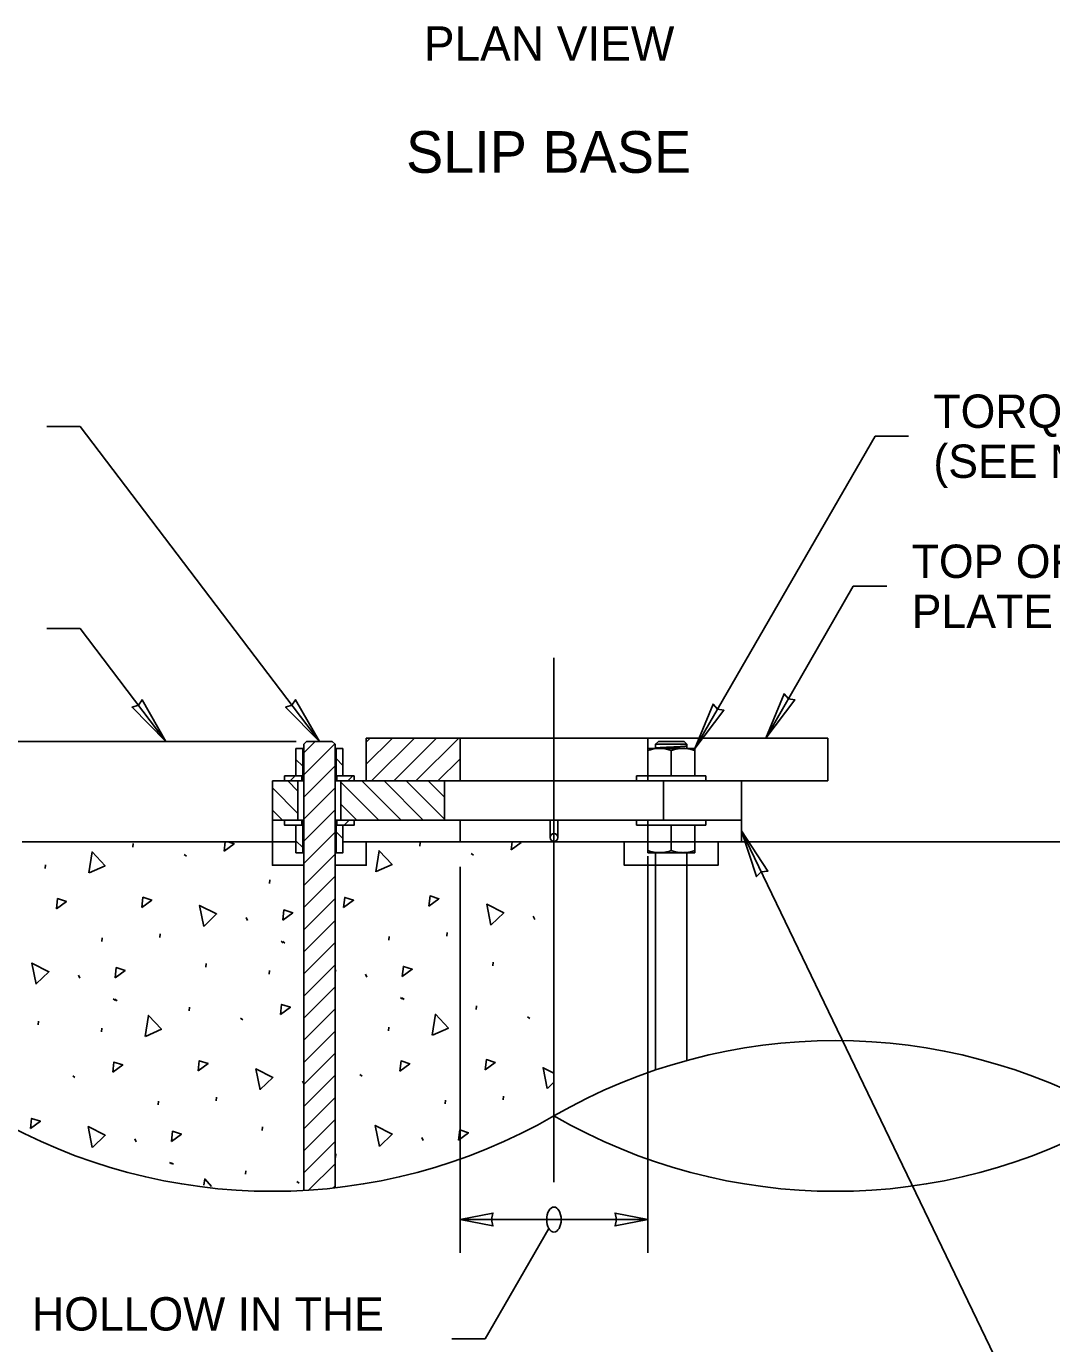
# Model space of a CAD drawing. Extents: x 99862 to 104211, y 98939 to 102076.
# Drawn here: x 100841 to 101332, y 100339 to 100970 of the extents above; entities that cross this region are included whole.
import ezdxf

# ---------------------------------------------------------------- set-up
doc = ezdxf.new("R2010")
doc.units = 0
for name, color, linetype in [('Level 1', 7, 'Continuous'), ('Level 12', 7, 'Continuous'), ('Level 13', 7, 'Continuous'), ('Level 15', 7, 'Continuous'), ('Level 20', 7, 'Continuous'), ('Level 3', 7, 'Continuous'), ('Level 4', 7, 'Continuous'), ('Level 62', 7, 'Continuous'), ('Level 8', 7, 'Continuous'), ('Level 9', 7, 'Continuous')]:
    doc.layers.add(name, color=color, linetype=linetype)

msp = doc.modelspace()

# ---------------------------------------------------------------- linework, layer by layer
at = {"layer": 'Level 1'}
for centre, start, end in [((101228.69, 100213.97), 60, 120), ((100958.69, 100681.63), 240, 300), ((101228.69, 100681.63), 240, 300)]:
    msp.add_arc(centre, 270, start, end, dxfattribs=at)
at = {"layer": 'Level 12'}
for p, q in [((100958.69, 100579.31), (100958.69, 100589.72)), ((101091.82, 100581.35), (101091.82, 100589.72)), ((101095.57, 100581.35), (101095.57, 100589.72)), ((101138.69, 100579.31), (101138.69, 100589.72)), ((101183.69, 100579.31), (101183.69, 100589.72))]:
    msp.add_line(p, q, dxfattribs=at)
for points in [[(100969.94, 100587.22), (100964.52, 100587.22), (100964.52, 100589.72), (100963.51, 100589.72), (100958.69, 100589.72), (100958.69, 100579.31), (100958.69, 100579.31), (100958.69, 100568.06), (100973.69, 100568.06), (100973.69, 100571.45), (100973.69, 100574.09), (100973.22, 100574.09), (100969.94, 100574.09), (100969.94, 100579.8), (100969.94, 100587.22)], [(100992.99, 100587.22), (100992.44, 100587.22), (100992.44, 100580.88), (100992.44, 100574.09), (100989.16, 100574.09), (100988.69, 100574.09), (100988.69, 100571.66), (100988.69, 100569.16), (100988.69, 100568.06), (101003.69, 100568.06), (101003.69, 100579.31), (101048.69, 100579.31), (101048.69, 100589.72), (101041.19, 100589.72), (101030.96, 100589.72), (101020.35, 100589.72), (101009.74, 100589.72), (100999.14, 100589.72), (100997.86, 100589.72), (100997.86, 100587.22), (100992.99, 100587.22)], [(101172.44, 100579.31), (101183.69, 100579.31), (101183.69, 100589.72), (101138.69, 100589.72), (101093.69, 100589.72), (101093.69, 100579.31), (101127.44, 100579.31), (101172.44, 100579.31)], [(101161.46, 100579.31), (101138.69, 100579.31), (101138.41, 100579.31), (101127.44, 100579.31), (101127.44, 100568.06), (101172.44, 100568.06), (101172.44, 100579.31), (101161.46, 100579.31)]]:
    msp.add_lwpolyline(points, dxfattribs=at)
msp.add_circle((101093.69, 100581.35), 1.88, dxfattribs=at)
at = {"layer": 'Level 13'}
for p, q in [((100891.68, 100576.69), (100891.83, 100578.43)), ((101029.37, 100577.26), (101029.52, 100579)), ((100916.37, 100573.17), (100917.39, 100572.39)), ((101054.06, 100573.74), (101055.08, 100572.97)), ((100849.71, 100566.55), (100849.86, 100568.3)), ((100957.23, 100559.25), (100957.38, 100560.99)), ((100946.06, 100542.98), (100946.75, 100541.53)), ((101083.76, 100543.56), (101084.44, 100542.11)), ((100876.79, 100531.55), (100876.94, 100533.29)), ((100904.69, 100533.45), (100904.84, 100535.2)), ((101014.48, 100532.13), (101014.63, 100533.87)), ((101042.38, 100534.03), (101042.53, 100535.77)), ((100962.78, 100531.67), (100963.8, 100530.89)), ((100963.58, 100531.52), (100964.6, 100530.74)), ((100926.68, 100519.24), (100926.83, 100520.98)), ((101064.37, 100519.81), (101064.52, 100521.56)), ((100865.62, 100515.29), (100866.31, 100513.83)), ((100957.16, 100515.81), (100957.31, 100517.55)), ((101003.32, 100515.86), (101004, 100514.41)), ((100882.34, 100503.97), (100883.36, 100503.19)), ((100883.14, 100503.82), (100884.16, 100503.04)), ((101020.03, 100504.55), (101021.05, 100503.77)), ((101020.84, 100504.4), (101021.85, 100503.62)), ((100918.69, 100498.24), (100918.84, 100499.99)), ((101056.38, 100498.82), (101056.53, 100500.56)), ((101081.07, 100495.3), (101082.09, 100494.52)), ((100846.24, 100491.54), (100846.39, 100493.28)), ((100876.72, 100488.11), (100876.87, 100489.85)), ((100943.38, 100494.72), (100944.4, 100493.95)), ((101014.41, 100488.69), (101014.56, 100490.43)), ((100862.94, 100467.03), (100863.96, 100466.25)), ((100973.07, 100464.54), (100973.69, 100463.24)), ((101000.63, 100467.6), (101001.65, 100466.83)), ((101069.39, 100455.59), (101069.54, 100457.33)), ((100903.8, 100453.11), (100903.95, 100454.85)), ((100931.7, 100455.01), (100931.85, 100456.75)), ((101041.49, 100453.68), (101041.64, 100455.43)), ((100953.69, 100440.79), (100953.84, 100442.54)), ((100892.63, 100436.84), (100893.32, 100435.39)), ((101030.33, 100437.42), (101031.01, 100435.97)), ((100909.35, 100425.53), (100910.37, 100424.75)), ((100988.95, 100427.89), (100989.1, 100429.63)), ((100910.15, 100425.38), (100911.17, 100424.6)), ((100945.7, 100419.8), (100945.85, 100421.54)), ((100970.39, 100416.28), (100971.41, 100415.5))]:
    msp.add_line(p, q, dxfattribs=at)
for points in [[(100935.51, 100574.87), (100936.02, 100579.31)], [(100937.48, 100579.31), (100940.3, 100578.4), (100935.51, 100574.87)], [(101073.2, 100575.45), (101073.65, 100579.31)], [(101076.96, 100579.31), (101077.99, 100578.98), (101073.2, 100575.45)], [(100870.57, 100564.35), (100872.16, 100574.47), (100878.4, 100567.79), (100870.74, 100564.4)], [(101008.26, 100564.92), (101009.85, 100575.05), (101016.09, 100568.37), (101008.43, 100564.98)], [(100855.07, 100547.17), (100855.64, 100552.07), (100859.86, 100550.7), (100855.07, 100547.17)], [(100896.01, 100547.85), (100896.58, 100552.74), (100900.81, 100551.37), (100896.01, 100547.85)], [(100992.76, 100547.75), (100993.33, 100552.64), (100997.55, 100551.28), (100992.76, 100547.75)], [(101033.7, 100548.42), (101034.27, 100553.31), (101038.5, 100551.95), (101033.7, 100548.42)], [(100925.71, 100538.75), (100923.74, 100548.81), (100931.89, 100544.67), (100925.85, 100538.86)], [(100963.64, 100541.73), (100964.21, 100546.62), (100968.43, 100545.26), (100963.64, 100541.73)], [(101063.41, 100539.33), (101061.43, 100549.38), (101069.58, 100545.24), (101063.54, 100539.44)], [(100845.27, 100511.05), (100843.3, 100521.11), (100851.45, 100516.97), (100845.41, 100511.17)], [(100883.2, 100514.03), (100883.77, 100518.93), (100887.99, 100517.56), (100883.2, 100514.03)], [(100988.69, 100517.78), (100989.14, 100517.55), (100988.69, 100517.11)], [(101020.89, 100514.61), (101021.46, 100519.5), (101025.69, 100518.14), (101020.89, 100514.61)], [(100962.52, 100496.43), (100963.09, 100501.32), (100967.31, 100499.96), (100962.52, 100496.43)], [(100897.58, 100485.9), (100899.17, 100496.03), (100905.41, 100489.35), (100897.75, 100485.96)], [(101035.27, 100486.48), (101036.86, 100496.6), (101043.1, 100489.93), (101035.44, 100486.54)], [(100882.08, 100468.73), (100882.65, 100473.62), (100886.87, 100472.26), (100882.08, 100468.73)], [(100923.02, 100469.4), (100923.59, 100474.29), (100927.82, 100472.93), (100923.02, 100469.4)], [(100952.72, 100460.31), (100950.75, 100470.36), (100958.9, 100466.23), (100952.86, 100460.42)], [(101019.77, 100469.31), (101020.34, 100474.2), (101024.56, 100472.84), (101019.77, 100469.31)], [(101060.71, 100469.98), (101061.28, 100474.87), (101065.51, 100473.51), (101060.71, 100469.98)], [(101090.42, 100460.88), (101088.44, 100470.94), (101093.69, 100468.28)], [(101093.69, 100464.01), (101090.55, 100461)], [(100842.58, 100441.7), (100843.15, 100446.6), (100847.38, 100445.23), (100842.58, 100441.7)], [(100872.28, 100432.61), (100870.31, 100442.67), (100878.46, 100438.53), (100872.42, 100432.72)], [(100910.21, 100435.59), (100910.78, 100440.48), (100915, 100439.12), (100910.21, 100435.59)], [(101009.98, 100433.19), (101008, 100443.24), (101016.15, 100439.1), (101010.11, 100433.3)], [(101047.9, 100436.17), (101048.47, 100441.06), (101052.7, 100439.7), (101047.9, 100436.17)], [(100925.69, 100414.51), (100926.18, 100417.59), (100929.51, 100414.02)]]:
    msp.add_lwpolyline(points, dxfattribs=at)
at = {"layer": 'Level 15'}
for p, q in [((100850.4, 100778.53), (100866.4, 100778.53)), ((100981.19, 100627.44), (100866.4, 100778.53)), ((101161.19, 100624.09), (101247.67, 100773.87)), ((101247.67, 100773.87), (101263.67, 100773.87)), ((101195.25, 100629.09), (101237.27, 100701.87)), ((101237.27, 100701.87), (101253.27, 100701.87)), ((100850.4, 100681.6), (100866.4, 100681.6)), ((100907.55, 100627.44), (100866.4, 100681.6)), ((100970.05, 100627.44), (100775.27, 100627.44)), ((101183.69, 100584.51), (101310.37, 100321.47)), ((101138.69, 100572.34), (101138.69, 100382.09)), ((101048.69, 100567.31), (101048.69, 100382.09)), ((101091.24, 100393.85), (101060.64, 100340.85)), ((101044.64, 100340.85), (101060.64, 100340.85))]:
    msp.add_line(p, q, dxfattribs=at)
for points in [[(100907.55, 100627.44), (100891.37, 100643.81), (100894.38, 100644.78), (100896.12, 100647.42)], [(100981.19, 100627.44), (100965, 100643.81), (100968.02, 100644.78), (100969.76, 100647.42)], [(101195.25, 100629.09), (101204.08, 100650.35), (101206.14, 100647.95), (101209.25, 100647.37)], [(101161.19, 100624.09), (101170.02, 100645.35), (101172.07, 100642.95), (101175.19, 100642.37)], [(101183.69, 100584.51), (101196.29, 100565.24), (101193.14, 100564.9), (101190.91, 100562.65)]]:
    msp.add_lwpolyline(points, close=True, dxfattribs=at)
msp.add_ellipse((101093.69, 100398.09), major_axis=(0, -6), ratio=0.57735, dxfattribs=at)
at = {"layer": 'Level 3'}
for p, q in [((100958.69, 100608.47), (100958.69, 100589.72)), ((100970.88, 100608.47), (100958.69, 100608.47)), ((100958.69, 100605.14), (100970.88, 100592.95)), ((100965.97, 100608.47), (100970.88, 100603.55)), ((100970.88, 100608.47), (100970.88, 100589.72)), ((100970.88, 100608.47), (100973.69, 100608.47)), ((100988.69, 100608.47), (100991.5, 100608.47)), ((101003.69, 100608.47), (100991.5, 100608.47)), ((100991.5, 100608.47), (100991.5, 100589.72)), ((100991.5, 100607.95), (101009.74, 100589.72)), ((101001.6, 100608.47), (101020.35, 100589.72)), ((101012.21, 100608.47), (101030.96, 100589.72)), ((101022.81, 100608.47), (101041.19, 100590.09)), ((101033.42, 100608.47), (101041.19, 100600.69)), ((101041.19, 100589.72), (101041.19, 100608.47)), ((101183.69, 100608.47), (101048.69, 100608.47)), ((101146.19, 100589.72), (101146.19, 100608.47)), ((101183.41, 100608.47), (101183.69, 100608.19)), ((101183.69, 100589.72), (101183.69, 100608.47)), ((100991.5, 100597.35), (100999.14, 100589.72)), ((100958.69, 100594.53), (100963.51, 100589.72)), ((100958.69, 100589.72), (100970.88, 100589.72)), ((100970.88, 100589.72), (100973.69, 100589.72)), ((100988.69, 100589.72), (100991.5, 100589.72)), ((100991.5, 100589.72), (101041.19, 100589.72)), ((101183.69, 100589.72), (101041.19, 100589.72))]:
    msp.add_line(p, q, dxfattribs=at)
at = {"layer": 'Level 4'}
for p, q in [((101048.69, 100629.09), (101003.69, 100629.09)), ((101003.69, 100608.47), (101003.69, 100629.09)), ((101003.69, 100627.17), (101005.61, 100629.09)), ((101003.69, 100616.56), (101016.22, 100629.09)), ((101006.2, 100608.47), (101026.83, 100629.09)), ((101016.81, 100608.47), (101037.43, 100629.09)), ((101027.41, 100608.47), (101048.04, 100629.09)), ((101048.69, 100608.47), (101048.69, 100629.09)), ((101093.69, 100629.09), (101048.69, 100629.09)), ((101224.98, 100629.09), (101093.69, 100629.09)), ((101138.69, 100608.47), (101138.69, 100629.09)), ((101224.98, 100608.47), (101224.98, 100629.09)), ((101038.02, 100608.47), (101048.69, 100619.14)), ((101048.69, 100608.47), (101003.69, 100608.47)), ((101048.63, 100608.47), (101048.69, 100608.53)), ((101224.98, 100608.47), (101183.69, 100608.47)), ((101138.69, 100398.09), (101048.69, 100398.09))]:
    msp.add_line(p, q, dxfattribs=at)
for points in [[(101048.69, 100398.09), (101064.42, 100395.01), (101063.69, 100398.09), (101064.42, 100401.18)], [(101138.69, 100398.09), (101122.97, 100395.01), (101123.69, 100398.09), (101122.97, 100401.18)]]:
    msp.add_lwpolyline(points, close=True, dxfattribs=at)
at = {"layer": 'Level 62'}
for points, degree in [([(100988.69, 100624.18), (100988.74, 100624.15), (100988.73, 100624.12), (100988.66, 100624.09)], 3), ([(101142.44, 100624.09), (101142.17, 100624.3), (101144.21, 100624.47), (101147.28, 100624.61), (101153.2, 100624.88), (101158.21, 100625.15), (101157.44, 100625.43)], 4), ([(101157.44, 100624.18), (101157.49, 100624.15), (101157.48, 100624.12), (101157.41, 100624.09)], 3), ([(100988.69, 100571.66), (100988.71, 100571.65), (100988.72, 100571.64), (100988.72, 100571.62)], 3), ([(101157.44, 100574), (101157.49, 100574.03), (101157.48, 100574.06), (101157.41, 100574.09)], 3), ([(101157.44, 100574), (101157.49, 100574.03), (101157.48, 100574.06), (101157.41, 100574.09)], 3), ([(100988.69, 100569.16), (100988.71, 100569.14), (100988.71, 100569.13), (100988.71, 100569.12)], 3)]:
    msp.add_open_spline(points, degree=degree, dxfattribs=at)
at = {"layer": 'Level 8'}
for p, q in [((101048.69, 100579.31), (101048.69, 100589.72)), ((100958.69, 100579.31), (100838.69, 100579.31)), ((100958.69, 100579.31), (100958.69, 100568.06)), ((100958.69, 100579.31), (100969.66, 100579.31)), ((101003.69, 100579.31), (100992.71, 100579.31)), ((101093.69, 100579.31), (101003.69, 100579.31)), ((101003.69, 100579.31), (101003.69, 100568.06)), ((101093.69, 100579.31), (101127.44, 100579.31)), ((101127.44, 100579.31), (101127.44, 100568.06)), ((101127.44, 100579.31), (101127.44, 100568.06)), ((101127.44, 100579.31), (101138.41, 100579.31)), ((101172.44, 100579.31), (101161.46, 100579.31)), ((101172.44, 100579.31), (101348.69, 100579.31)), ((101172.44, 100579.31), (101172.44, 100568.06)), ((101172.44, 100579.31), (101172.44, 100568.06)), ((100973.69, 100568.06), (100958.69, 100568.06)), ((101003.69, 100568.06), (100988.69, 100568.06)), ((101172.44, 100568.06), (101127.44, 100568.06)), ((101172.44, 100568.06), (101127.44, 100568.06))]:
    msp.add_line(p, q, dxfattribs=at)
at = {"layer": 'Level 9'}
for p, q in [((101093.69, 100667.59), (101093.69, 100416.08)), ((100969.94, 100624.09), (100973.22, 100624.09)), ((100969.94, 100624.09), (100969.94, 100610.97)), ((100973.22, 100624.09), (100973.22, 100608.47)), ((100975.02, 100627.44), (100973.69, 100626.11)), ((100973.69, 100621.99), (100979.14, 100627.44)), ((100973.69, 100611.38), (100988.56, 100626.25)), ((100973.69, 100626.11), (100973.69, 100412.04)), ((100975.02, 100627.44), (100987.37, 100627.44)), ((100988.69, 100626.11), (100987.37, 100627.44)), ((100988.69, 100413.3), (100988.69, 100626.11)), ((100989.16, 100624.09), (100992.44, 100624.09)), ((100989.16, 100608.47), (100989.16, 100624.09)), ((100992.44, 100624.09), (100992.44, 100610.97)), ((101138.69, 100624.09), (101155.44, 100624.09)), ((101138.69, 100623.08), (101138.69, 100610.97)), ((101143.77, 100627.44), (101142.44, 100626.11)), ((101142.44, 100626.11), (101157.44, 100626.11)), ((101142.44, 100626.11), (101142.44, 100624.09)), ((101143.77, 100627.44), (101156.12, 100627.44)), ((101149.94, 100623.09), (101149.94, 100610.97)), ((101155.69, 100624.09), (101155.44, 100624.09)), ((101155.69, 100624.09), (101161.19, 100624.09)), ((101157.44, 100626.11), (101156.12, 100627.44)), ((101157.44, 100624.09), (101157.44, 100626.11)), ((101161.19, 100623.09), (101161.19, 100610.97)), ((100969.94, 100618.81), (100973.22, 100615.53)), ((100973.69, 100600.77), (100988.69, 100615.77)), ((100989.16, 100619.26), (100992.44, 100615.98)), ((100964.52, 100610.97), (100964.52, 100608.47)), ((100972.75, 100610.97), (100964.52, 100610.97)), ((100967.1, 100608.47), (100969.6, 100610.97)), ((100972.75, 100610.97), (100972.75, 100608.47)), ((100973.22, 100610.97), (100972.75, 100610.97)), ((100989.63, 100610.97), (100989.16, 100610.97)), ((100989.63, 100608.47), (100989.63, 100610.97)), ((100997.86, 100610.97), (100989.63, 100610.97)), ((100994.8, 100608.47), (100997.3, 100610.97)), ((100997.86, 100610.97), (100997.86, 100608.47)), ((101166.61, 100610.97), (101133.27, 100610.97)), ((101133.27, 100610.97), (101133.27, 100608.47)), ((101149.94, 100610.97), (101138.69, 100610.97)), ((101161.19, 100610.97), (101149.94, 100610.97)), ((101166.61, 100610.97), (101166.61, 100608.47)), ((100973.69, 100590.17), (100988.69, 100605.17)), ((100973.69, 100579.56), (100988.69, 100594.56)), ((100964.52, 100587.22), (100964.52, 100589.72)), ((100972.75, 100587.22), (100964.52, 100587.22)), ((100969.94, 100574.09), (100969.94, 100587.22)), ((100972.23, 100587.22), (100972.75, 100587.74)), ((100972.75, 100587.22), (100972.75, 100589.72)), ((100973.22, 100587.22), (100972.75, 100587.22)), ((100973.22, 100587.22), (100973.22, 100589.72)), ((100973.22, 100574.09), (100973.22, 100587.22)), ((100973.69, 100568.95), (100988.69, 100583.95)), ((100989.16, 100589.72), (100989.16, 100587.22)), ((100992.44, 100587.22), (100989.16, 100587.22)), ((100989.16, 100587.22), (100989.16, 100574.09)), ((100989.16, 100584.15), (100992.44, 100580.88)), ((100989.63, 100589.72), (100989.63, 100587.22)), ((100992.44, 100574.09), (100992.44, 100587.22)), ((100997.86, 100587.22), (100992.44, 100587.22)), ((100992.99, 100587.22), (100995.49, 100589.72)), ((100997.86, 100587.22), (100997.86, 100589.72)), ((101133.27, 100587.22), (101133.27, 100589.72)), ((101133.27, 100587.22), (101133.27, 100589.72)), ((101166.61, 100587.22), (101133.27, 100587.22)), ((101166.61, 100587.22), (101133.27, 100587.22)), ((101138.69, 100575.1), (101138.69, 100587.22)), ((101138.69, 100575.1), (101138.69, 100587.22)), ((101149.94, 100575.09), (101149.94, 100587.22)), ((101149.94, 100575.09), (101149.94, 100587.22)), ((101161.19, 100575.09), (101161.19, 100587.22)), ((101161.19, 100575.09), (101161.19, 100587.22)), ((101166.61, 100587.22), (101166.61, 100589.72)), ((101166.61, 100587.22), (101166.61, 100589.72)), ((100969.94, 100579.8), (100973.22, 100576.52)), ((100969.94, 100574.09), (100973.22, 100574.09)), ((100973.22, 100574.09), (100973.69, 100574.09)), ((100973.69, 100558.35), (100988.69, 100573.35)), ((100988.69, 100574.09), (100989.16, 100574.09)), ((100989.16, 100574.09), (100992.44, 100574.09)), ((101138.69, 100574.09), (101155.44, 100574.09)), ((101138.69, 100574.09), (101155.44, 100574.09)), ((101142.44, 100469.82), (101142.44, 100574.09)), ((101155.69, 100574.09), (101155.44, 100574.09)), ((101155.69, 100574.09), (101155.44, 100574.09)), ((101155.69, 100574.09), (101161.19, 100574.09)), ((101155.69, 100574.09), (101161.19, 100574.09)), ((101157.44, 100474.4), (101157.44, 100574.09)), ((100973.69, 100547.74), (100988.69, 100562.74)), ((100973.69, 100537.13), (100988.69, 100552.13)), ((100973.69, 100526.53), (100988.69, 100541.53)), ((100973.69, 100515.92), (100988.69, 100530.92)), ((100973.69, 100505.31), (100988.69, 100520.31)), ((100973.69, 100494.71), (100988.69, 100509.71)), ((100973.69, 100484.1), (100988.69, 100499.1)), ((100973.69, 100473.49), (100988.69, 100488.49)), ((100973.69, 100462.89), (100988.69, 100477.89)), ((100973.69, 100452.28), (100988.69, 100467.28)), ((100973.69, 100441.67), (100988.69, 100456.67)), ((100973.69, 100431.07), (100988.69, 100446.07)), ((100973.69, 100420.46), (100988.69, 100435.46)), ((100976.02, 100412.18), (100988.69, 100424.85)), ((100987.62, 100413.18), (100988.69, 100414.25))]:
    msp.add_line(p, q, dxfattribs=at)
for points, degree in [([(101149.94, 100623.09), (101148.1, 100623.7), (101146.24, 100624.09), (101142.41, 100624.09), (101140.53, 100623.7), (101138.69, 100623.08)], 3), ([(101138.69, 100624.09), (101138.69, 100624.09), (101138.69, 100624.09), (101138.69, 100624.09)], 2), ([(101138.69, 100624.09), (101138.69, 100624.09), (101138.69, 100623.99), (101138.69, 100623.64), (101138.69, 100623.39), (101138.69, 100623.08)], 3), ([(101155.44, 100624.09), (101153.57, 100624.07), (101151.73, 100623.68), (101149.94, 100623.09)], 2), ([(101161.19, 100623.09), (101159.39, 100623.69), (101157.57, 100624.07), (101155.69, 100624.09)], 2), ([(101161.19, 100624.09), (101161.19, 100624.08), (101161.19, 100623.97), (101161.19, 100623.62), (101161.19, 100623.38), (101161.19, 100623.09)], 3), ([(101149.94, 100575.09), (101148.1, 100574.48), (101146.24, 100574.09), (101142.41, 100574.09), (101140.53, 100574.48), (101138.69, 100575.1)], 3), ([(101138.69, 100574.09), (101138.69, 100574.09), (101138.69, 100574.19), (101138.69, 100574.54), (101138.69, 100574.79), (101138.69, 100575.1)], 3), ([(101149.94, 100575.09), (101148.1, 100574.48), (101146.24, 100574.09), (101142.41, 100574.09), (101140.53, 100574.48), (101138.69, 100575.1)], 3), ([(101138.69, 100574.09), (101138.69, 100574.09), (101138.69, 100574.19), (101138.69, 100574.54), (101138.69, 100574.79), (101138.69, 100575.1)], 3), ([(101138.69, 100574.09), (101138.69, 100574.09), (101138.69, 100574.09), (101138.69, 100574.09)], 2), ([(101138.69, 100574.09), (101138.69, 100574.09), (101138.69, 100574.09), (101138.69, 100574.09)], 2), ([(101155.44, 100574.09), (101153.57, 100574.11), (101151.73, 100574.5), (101149.94, 100575.09)], 2), ([(101155.44, 100574.09), (101153.57, 100574.11), (101151.73, 100574.5), (101149.94, 100575.09)], 2), ([(101161.19, 100575.09), (101159.39, 100574.49), (101157.57, 100574.11), (101155.69, 100574.09)], 2), ([(101161.19, 100575.09), (101159.39, 100574.49), (101157.57, 100574.11), (101155.69, 100574.09)], 2), ([(101161.19, 100574.09), (101161.19, 100574.11), (101161.19, 100574.21), (101161.19, 100574.56), (101161.19, 100574.8), (101161.19, 100575.09)], 3), ([(101161.19, 100574.09), (101161.19, 100574.11), (101161.19, 100574.21), (101161.19, 100574.56), (101161.19, 100574.8), (101161.19, 100575.09)], 3)]:
    msp.add_open_spline(points, degree=degree, dxfattribs=at)

# ---------------------------------------------------------------- texts
at = {"layer": 'Level 12'}
msp.add_text('SLIP BASE', height=20, dxfattribs=at).set_placement((101022.75, 100900.23))
at = {"layer": 'Level 20'}
for s, height, p in [('PLAN VIEW', 16.5, (101031.27, 100953.98)), ('TORQUE ANCHOR BOLTS', 16, (101275.67, 100777.87)), ('(SEE NOTE 4)', 16, (101275.67, 100753.87)), ('TOP OF ANCHOR/SLIP', 16, (101265.27, 100705.87)), ('PLATE ASSEMBLY', 16, (101265.27, 100681.87)), ('    LEAVE    6" (IN) HOLLOW IN THE', 16, (100659.75, 100344.85))]:
    msp.add_text(s, height=height, dxfattribs=at).set_placement(p)

doc.saveas('drawing.dxf')
